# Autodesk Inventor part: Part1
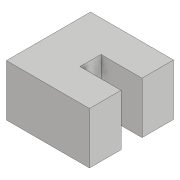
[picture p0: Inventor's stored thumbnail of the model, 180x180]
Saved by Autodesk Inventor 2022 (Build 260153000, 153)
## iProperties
Created: 2015-07
Part Number: Part1
Material: Generic
Document SubType Name: Modeling
Designer: Sandeep
Density: 1 g/cm^3
Appearance: Default
Author: Sandeep
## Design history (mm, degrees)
sketch "Sketch1"
  geometry: L1 (0, 0)-(-30, 0); L2 (-30, 0)-(-30, 40); L3 (-30, 40)-(0, 40); L4 (0, 40)-(0, 0)
  constraints: 8 end point, 2 parallel, 1 horizontal, 1 perpendicular
  dimensions: "d0" = 30 distance between parallel lines of L4 L2; "d1" = 40 distance of L1.end L2.end
extrude "Extrusion1" new body sketch "Sketch1" distance "d2" = 15; taper "d3" = 0 deg
sketch "Sketch2"
  geometry: L1 (0, 40)-(0, 0) reference; L2 (-15, 0)-(-15, 40) reference; L3 (0, 0)-(-15, 0) reference; L4 (-15, 15)-(0, 15); L5 (0, 15)-(0, 25); L6 (0, 25)-(-15, 25); L7 (-15, 25)-(-15, 15)
  constraints: 8 end point, 2 parallel, 2 point on line, 1 horizontal, 1 perpendicular
  dimensions: "d4" = 10 distance between parallel lines of L6 L4; "d5" = 15 distance between parallel lines of L3 L4
extrude "Extrusion2" cut sketch "Sketch2" distance "d6" = 10; taper "d7" = 0 deg
node "Direct Edit2"
body "Solid1"
feature "Size2" dims "d9" = 9.5
